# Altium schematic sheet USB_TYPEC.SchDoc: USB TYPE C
size A3; Date: Not used; ApprovedBy: Not used; CheckedBy: Not used; Author: Not used; CompanyName: STMicroelectronics; DrawnBy: Not used; Engineer: Not used; Organization: Not used; Address1: Not used; Address2: Not used; Address3: Not used; Address4: Not used; DocumentNumber: 9; Revision: Not used; SheetNumber: 9; SheetTotal: 16
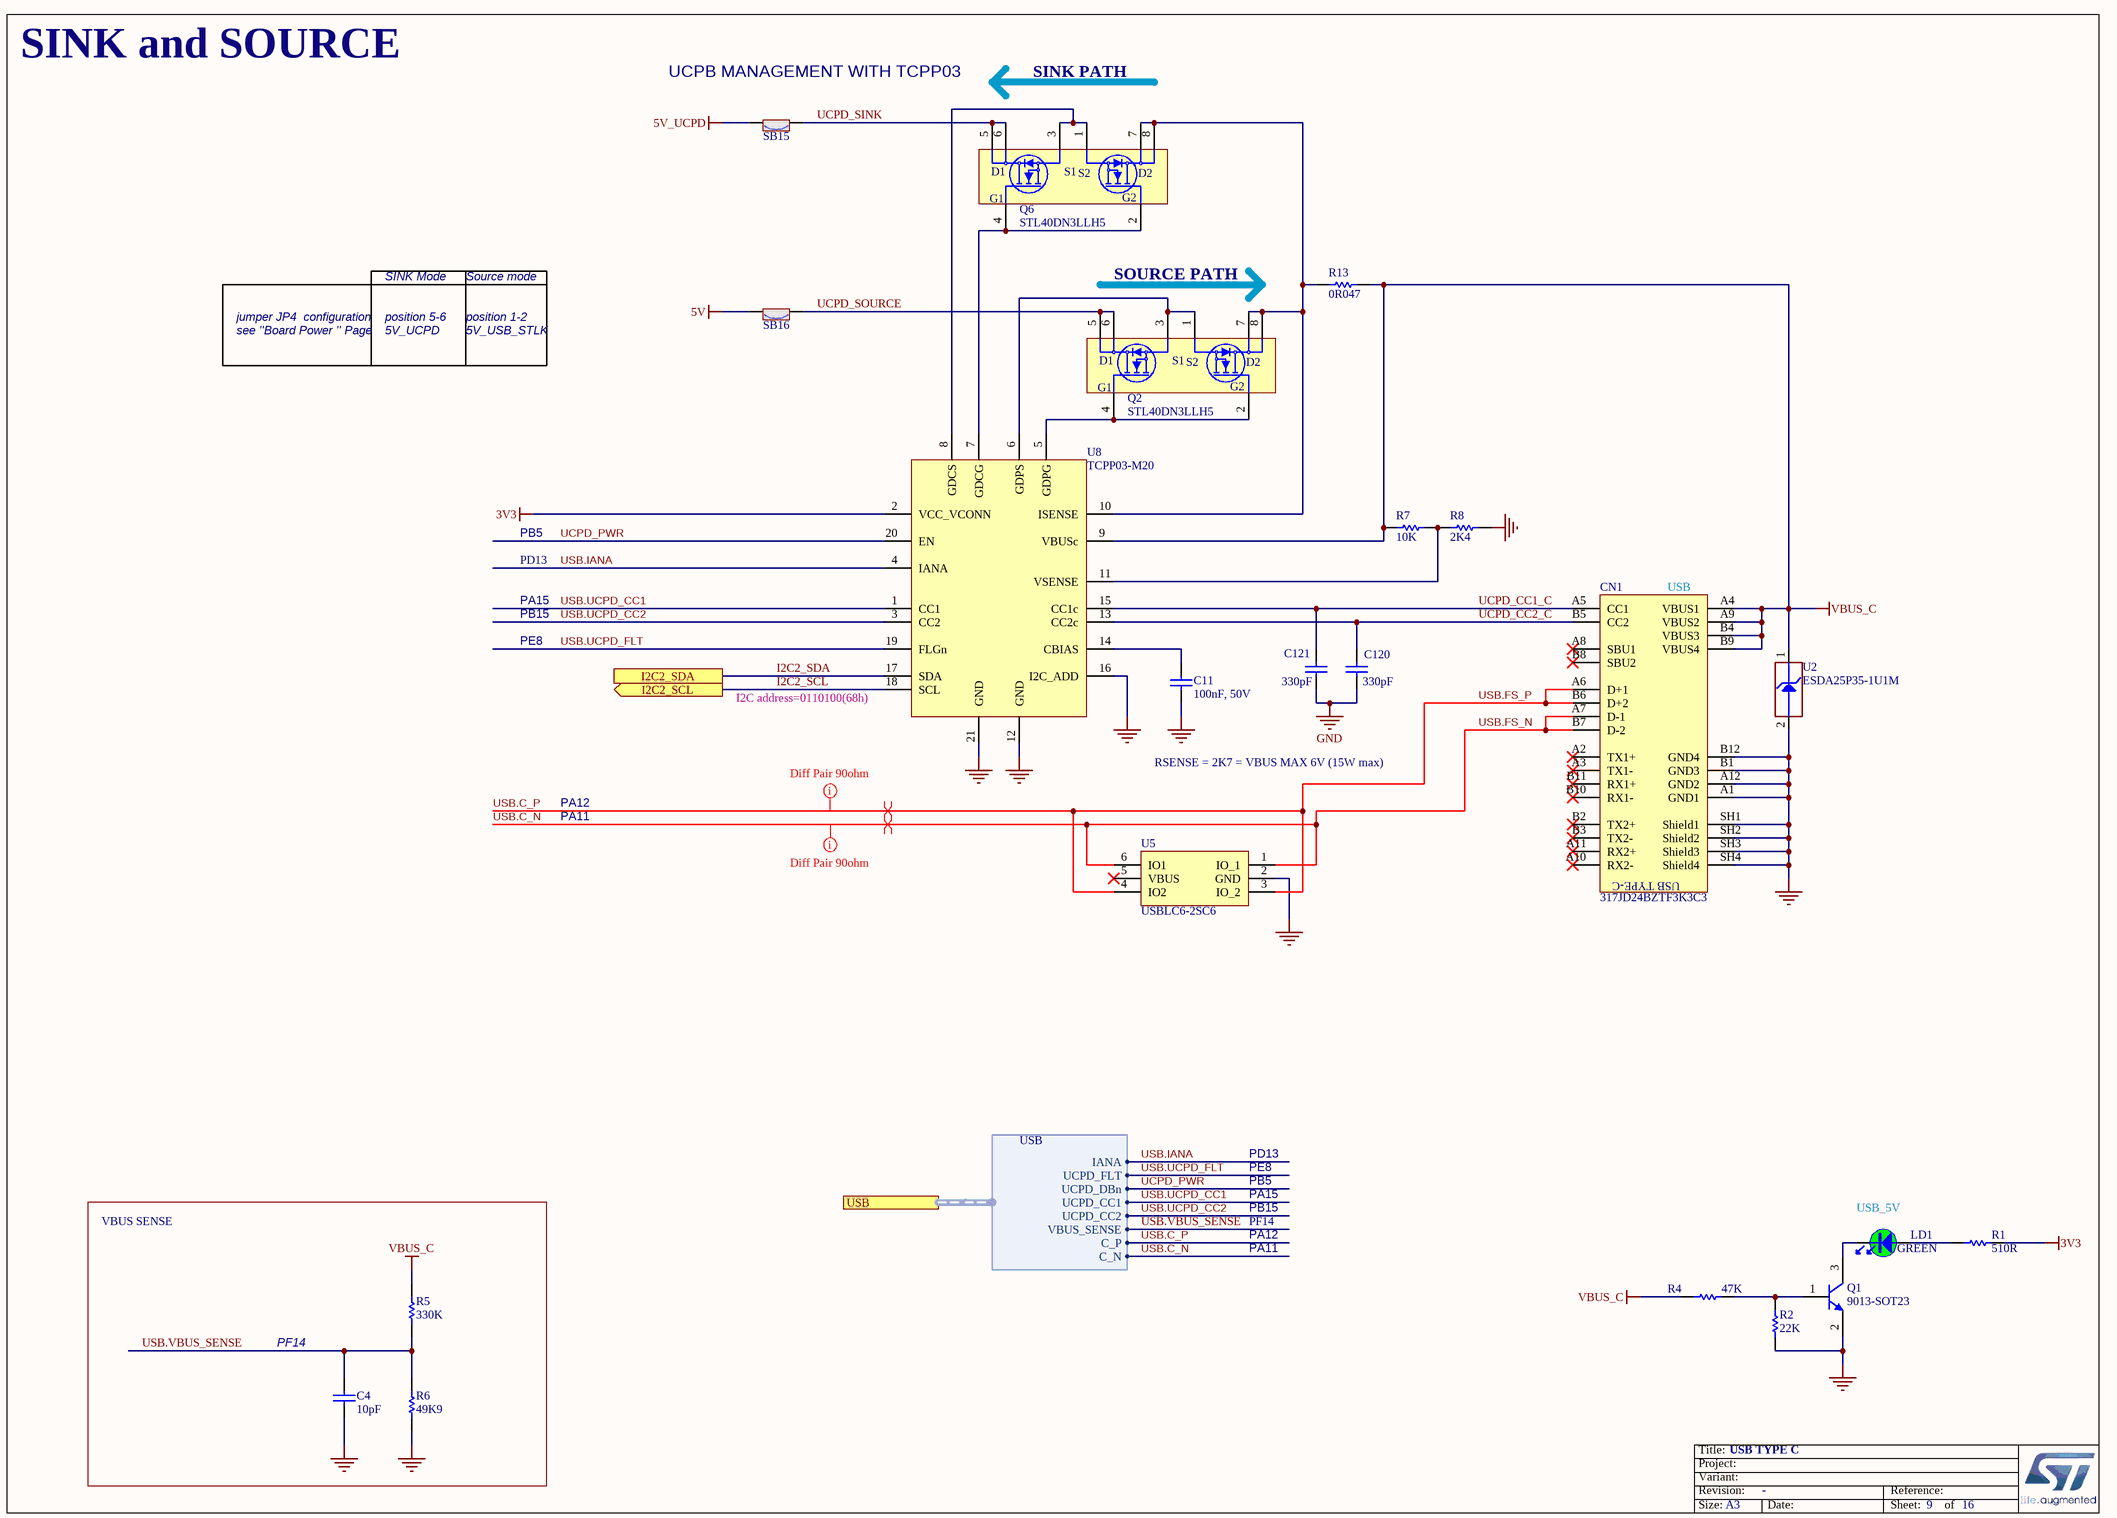
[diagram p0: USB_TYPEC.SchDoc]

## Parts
C4  value 10pF  [C0603]
C11  value 100nF, 50V  [C0603]
C120  value 330pF  [C0402]  (hidden comment: Capacitor)
C121  value 330pF  [C0402]  (hidden comment: Capacitor)
CN1  value 317JD24BZTF3K3C3  [CON_USB-TYPEC_COXOC_317JD24BZTF3K3C3]  (hidden comment: USB_TYPE_C_Receptacle_317JD24BZTF3K3C3)
LD1  value GREEN  [LED_0603_GREEN]
Q1  value 9013-SOT23  [NPN_SOT23]
Q2  STL40DN3LLH5  [PowerFLAT_5x6]
Q6  STL40DN3LLH5  [PowerFLAT_5x6]
R1  value 510R  [R0603]
R2  value 22K  [R0603]
R4  value 47K  [R0603]
R5  value 330K  [R0603]
R6  value 49K9  [R0603]
R7  value 10K  [R0603]
R8  value 2K4  [R0402]  (hidden comment: Resistor)
R13  value 0R047  [R0805_H0P5]  (hidden comment: Resistor)
SB15  (no value)  [SOLDER-BRIDGE_R0603-0R]
SB16  (no value)  [SOLDER-BRIDGE_R0603-0R]
U2  value ESDA25P35-1U1M  [ESD_QFN1610_2N_1K_2A]  (hidden comment: ESD-TRANSIL)
U5  USBLC6-2SC6  [ESD_SOT23-6L]
U8  TCPP03-M20  [ICC_QFN20-EPAD_4X4_P050]

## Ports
I2C2_SCL (out), I2C2_SDA, USB (harness USB)

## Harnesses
USB: UCPD_FLT, UCPD_DBn, UCPD_CC2, VBUS_SENSE, C_P, C_N, UCPD_CC1, IANA

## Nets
3V3: R1.1 U8.2(VCC_VCONN)
5V: SB16.2
5V_UCPD: SB15.2
GND: C4.1 C11.2 C120.1 C121.1 CN1.A1(GND1) CN1.A12(GND2) CN1.B1(GND3) CN1.B12(GND4) CN1.SH1(Shield1) CN1.SH2(Shield2) CN1.SH3(Shield3) CN1.SH4(Shield4) Q1.2(E) R2.1 R6.1 R8.2 U2.2(GND) U5.2(GND) U8.12(GND) U8.16(I2C_ADD) U8.21(GND)
VBUS_C: CN1.A4(VBUS1) CN1.A9(VBUS2) CN1.B4(VBUS3) CN1.B9(VBUS4) R4.1 R5.2 R7.2 R13.1 U2.1(IO1) U8.9(VBUSc)
I2C2_SCL: U8.18(SCL) ; port I2C2_SCL
I2C2_SDA: U8.17(SDA) ; port I2C2_SDA
UCPD_CC1_C: C121.2 CN1.A5(CC1) U8.15(CC1c)
UCPD_CC2_C: C120.2 CN1.B5(CC2) U8.13(CC2c)
UCPD_PWR: U8.20(EN) ; port USB.UCPD_DBn
UCPD_SINK: Q6.5(D1) Q6.6(D1) SB15.1
UCPD_SOURCE: Q2.5(D1) Q2.6(D1) SB16.1
USB.C_N: CN1.A7(D-1) CN1.B7(D-2) U5.1(IO_1) U5.6(IO1) ; port USB.C_N  [also labelled USB.FS_N]
USB.C_P: CN1.A6(D+1) CN1.B6(D+2) U5.3(IO_2) U5.4(IO2) ; port USB.C_P  [also labelled USB.FS_P]
USB.IANA: U8.4(IANA) ; port USB.IANA
USB.UCPD_CC1: U8.1(CC1) ; port USB.UCPD_CC1
USB.UCPD_CC2: U8.3(CC2) ; port USB.UCPD_CC2
USB.UCPD_FLT: U8.19(FLGn) ; port USB.UCPD_FLT
USB.VBUS_SENSE: C4.2 R5.1 R6.2 ; port USB.VBUS_SENSE
NetC11_1: C11.1 U8.14(CBIAS)
NetLD1_1: LD1.1 R1.2
NetLD1_2: LD1.2 Q1.3(C)
NetQ1_1: Q1.1(B) R2.2 R4.2
NetQ2_1: Q2.1(S2) Q2.3(S1) U8.6(GDPS)
NetQ2_2: Q2.2(G2) Q2.4(G1) U8.5(GDPG)
NetQ2_7: Q2.7(D2) Q2.8(D2) Q6.7(D2) Q6.8(D2) R13.2 U8.10(ISENSE)
NetQ6_1: Q6.1(S2) Q6.3(S1) U8.8(GDCS)
NetQ6_2: Q6.2(G2) Q6.4(G1) U8.7(GDCG)
NetR7_1: R7.1 R8.1 U8.11(VSENSE)

Not connected (* = marked no-connect by the designer): CN1 A2(TX1+)* A3(TX1-)* A8(SBU1)* A10(RX2-)* A11(RX2+)* B2(TX2+)* B3(TX2-)* B8(SBU2)* B10(RX1-)* B11(RX1+)*; U5 5(VBUS)*

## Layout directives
mark named Diff Pair 90ohm: USB.C_N, USB.C_P
differential pair: USB.C_N, USB.C_P

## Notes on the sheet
- SINK and SOURCE
- (near SB15) UCPB MANAGEMENT WITH TCPP03
- SINK PATH
- jumper JP4  configuration
- position 5-6
- SINK Mode
- Source mode
- position 1-2
- SOURCE PATH
- see ''Board Power '' Page
- 5V_UCPD
- 5V_USB_STLK
- PB5
- PD13
- (near CN1) USB
- PA15
- PB15
- PE8
- (near U8) I2C address=0110100(68h)
- RSENSE = 2K7 = VBUS MAX 6V (15W max)
- PA12
- PA11
- VBUS SENSE
- PF14
- (near LD1) USB_5V

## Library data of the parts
C4 = MCD-00637: Capacitor, MLCC, 10pF, 50V, NPO, 5%, 0603, T=0,8mm; Manufacturer_Part_Number: CC0603JRNPO9BN100; Manufacturer: YAGEO; Provided_By: subcon; Initial_Board_Reference: MB1319
C11 = MCD-01099: Capacitor,100nF,50V,X7R,10%,0603; Manufacturer_Part_Number: CC0603KRX7R9BB104; Manufacturer: YAGEO; BMS_Part_Number: 9142278; Provided_By: SUBCO
C120 C121 = MCD-01579: Capacitor, MLCC, 330pF, 50V, NPO, +/-5%, 0402, T=0,5mm; Part_Preference: Recommended; Manufacturer: YAGEO; Manufacturer_Part_Number: CC0402JRNPO9BN331
CN1 = MCD-01108: USB tyce C certified receptacle for 1.6mm pcb height; Part_Type: Connector; Manufacturer: CHANT SINCERE (COXOC); Provided_By: SUBCO
LD1 = MCD-00050: LED, Green, 0603; Part_Type: Display; Manufacturer_Part_Number: 19-213SYGC/S530-E2/TR8; Manufacturer: EVERLIGHT; ECCN_US: EAR99; ECCN_EU: NEC; Provided_By: Subcon; Initial_Board_Reference: MB1274
Q1 = MCD-00073: NPN Bipolar Transistor; Part_Type: IC; Manufacturer_Part_Number: BSR14; Manufacturer: NXP; ECCN_US: EAR99; ECCN_EU: NEC; Provided_By: Subcon; Initial_Board_Reference: MB1274
Q2 Q6 = MCD-02152: Dual N-channel 30 V, 0.016 Ω typ., 40 A, STripFET™ H5 Power MOSFET; Part_Type: Transistor; Manufacturer: STMICROELECTRONICS; ECCN_US: EAR99; ECCN_EU: NEC; Provided_By: SUBCO
R1 = MCD-00225: Resistor,510R,0603,1%,1/10W; Manufacturer_Part_Number: RC0603FR-07510RL; Manufacturer: YAGEO; Provided_By: Subcon; Initial_Board_Reference: MB1319
R2 = MCD-00430: Resistor,22K,0603,1%,1/10W; Manufacturer_Part_Number: RC0603FR-0722KL; Manufacturer: YAGEO; Provided_By: Subcon
R4 = MCD-00222: Resistor,47K,0603,1%,1/10W; Manufacturer_Part_Number: RC0603FR-0747KL; Manufacturer: YAGEO; Provided_By: Subcon; Initial_Board_Reference: MB1319
R5 = MCD-00458: Resistor,330K,0603,1%,1/10W; Manufacturer_Part_Number: RC0603FR-07330KL; Manufacturer: YAGEO; Provided_By: Subcon
R6 = MCD-01171: Resistor,49K9,0603,1%; Manufacturer_Part_Number: RC0603FR-0749K9L; Manufacturer: YAGEO; Provided_By: Subcon; Initial_Board_Reference: MB1397
R7 = MCD-00220: Resistor,10K,0603,1%,1/10W; Manufacturer_Part_Number: RC0603FR-0710KL; Manufacturer: YAGEO; Provided_By: Subcon; Initial_Board_Reference: MB1319
R8 = MCD-00433: Resistor,2K4,0402,1%,1/16W; Part_Preference: Recommended; Manufacturer: YAGEO; Manufacturer_Part_Number: RC0402FR-072K4L
R13 = MCD-02151: Current Detection Resistor, 0R047, 0805, 1%, 1/4W; Manufacturer_Part_Number: RL0805FR-7W0R047L; Manufacturer: YAGEO; ECCN_US: NEC; ECCN_EU: EAR99; Provided_By: SUBCO
SB15 SB16 = MCD-00071: Solder Bridge ON; Part_Type: Mechanical; Provided_By: Subcon; Initial_Board_Reference: mb1274
U2 = MCD-01207: High power Transient voltage suppressor:25V/35A EOS and ESD transients protection.; Part_Type: Diode; Manufacturer: STMICROELECTRONICS; BMS_Part_Number: 9179045; ECCN_US: EAR99; ECCN_EU: NEC; Provided_By: SUBCO with ST control
U5 = MCD-00163: Very low capacitance ESD protection; Part_Type: IC; Manufacturer: STMICROELECTRONICS; BMS_Part_Number: 9151075; ECCN_US: EAR99; ECCN_EU: NEC; Provided_By: SUBCO with ST control
U8 = MCD-02130: USB Type-C Port Protection for USB DRP Power Delivery, PPS compliant; Part_Type: IC; Manufacturer: STMICROELECTRONICS; ECCN_US: EAR99; ECCN_EU: NEC; Provided_By: SUBCO with ST control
